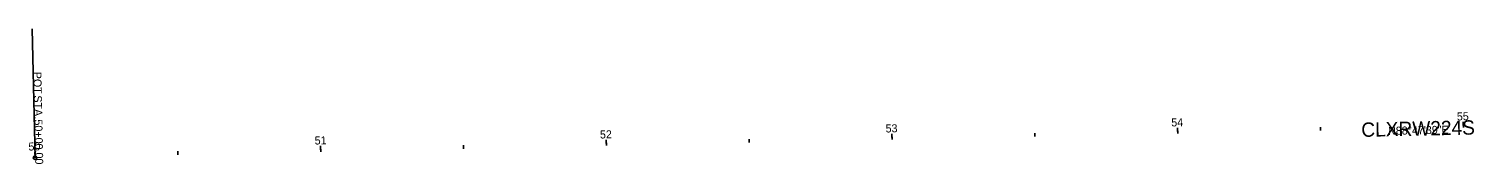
# Model space of a CAD drawing. Extents: x 2402033 to 2407435, y 498456 to 498900.
# Drawn here: x 2402033 to 2402538, y 498643 to 498690 of the extents above; entities that cross this region are included whole.
import ezdxf

# ---------------------------------------------------------------- set-up
doc = ezdxf.new("R2010")
doc.units = 0
for name, color, linetype in [('DR_P_Ditch', 7, 'Continuous'), ('DT_P_Graded_Shoulder', 7, 'Continuous'), ('DV_X_Property_Line', 7, 'Continuous'), ('MD_P_DNC', 7, 'Continuous'), ('MD_P_GRADE_BREAK', 7, 'Continuous'), ('RW_P_Esmt_CH', 7, 'Continuous'), ('RW_P_Esmt_SH', 7, 'Continuous'), ('RW_P_Esmt_TMP', 7, 'Continuous'), ('RW_X_CL_1000_Distances', 7, 'Continuous'), ('RW_X_Esmt_RR', 7, 'Continuous'), ('RW_X_Esmt_SH', 7, 'Continuous'), ('RW_X_Parent_Tract_Area', 7, 'Continuous')]:
    doc.layers.add(name, color=color, linetype=linetype)

msp = doc.modelspace()

# ---------------------------------------------------------------- linework, layer by layer
at = {"layer": 'DR_P_Ditch'}
for p, q in [((2402534.58, 498655.93), (2402534.55, 498657.13)), ((2402034.69, 498645.41), (2402034.65, 498647.41))]:
    msp.add_line(p, q, dxfattribs=at)
at = {"layer": 'DV_X_Property_Line'}
msp.add_line((2402034.69, 498645.41), (2402033.74, 498690.4), dxfattribs=at)
msp.add_circle((2402034.69, 498645.41), 0.6, dxfattribs=at)
at = {"layer": 'RW_P_Esmt_CH'}
for p, q in [((2402534.58, 498655.93), (2402534.54, 498657.93)), ((2402334.62, 498651.72), (2402334.6, 498652.92)), ((2402434.6, 498653.83), (2402434.57, 498655.02)), ((2402034.69, 498645.41), (2402034.65, 498647.41)), ((2402134.67, 498647.51), (2402134.64, 498648.71)), ((2402234.64, 498649.62), (2402234.62, 498650.82))]:
    msp.add_line(p, q, dxfattribs=at)
at = {"layer": 'RW_P_Esmt_SH'}
msp.add_line((2402034.69, 498645.41), (2402033.74, 498690.4), dxfattribs=at)
msp.add_circle((2402034.69, 498645.41), 0.6, dxfattribs=at)
at = {"layer": 'RW_X_Esmt_SH'}
for p, q in [((2402534.58, 498655.93), (2402534.54, 498657.93)), ((2402334.62, 498651.72), (2402334.58, 498653.72)), ((2402384.61, 498652.77), (2402384.59, 498653.97)), ((2402434.6, 498653.83), (2402434.56, 498655.82)), ((2402484.59, 498654.88), (2402484.56, 498656.08)), ((2402034.69, 498645.41), (2402034.65, 498647.41)), ((2402084.68, 498646.46), (2402084.65, 498647.66)), ((2402134.67, 498647.51), (2402134.62, 498649.51)), ((2402184.65, 498648.56), (2402184.63, 498649.76)), ((2402234.64, 498649.62), (2402234.6, 498651.62)), ((2402284.63, 498650.67), (2402284.61, 498651.87))]:
    msp.add_line(p, q, dxfattribs=at)
at = {"layer": 'RW_X_Parent_Tract_Area'}
msp.add_line((2402034.69, 498645.41), (2402033.74, 498690.4), dxfattribs=at)
msp.add_circle((2402034.69, 498645.41), 0.6, dxfattribs=at)

# ---------------------------------------------------------------- texts
at = {"layer": 'DR_P_Ditch'}
msp.add_text('50', height=2.8, rotation=1.2059, dxfattribs=at).set_placement((2402032.41, 498647.9))
at = {"layer": 'DT_P_Graded_Shoulder'}
msp.add_text('CLXRW224S', height=5, rotation=1.2059, dxfattribs=at).set_placement((2402498.92, 498652.68))
at = {"layer": 'DV_X_Property_Line'}
for s, p in [('POT', (2402034.1, 498675.4)), (' STA. ', (2402034.25, 498668.2)), ('50+00.00', (2402034.45, 498658.75))]:
    msp.add_text(s, height=2.8, rotation=271.2059, dxfattribs=at).set_placement(p)
at = {"layer": 'MD_P_DNC'}
msp.add_text('CLXRW224S', height=5, rotation=1.2059, dxfattribs=at).set_placement((2402498.92, 498652.68))
at = {"layer": 'MD_P_GRADE_BREAK'}
msp.add_text('CLXRW224S', height=5, rotation=1.2059, dxfattribs=at).set_placement((2402498.92, 498652.68))
at = {"layer": 'RW_P_Esmt_CH'}
for s, p in [('55', (2402532.34, 498658.42)), ('50', (2402032.41, 498647.9))]:
    msp.add_text(s, height=2.8, rotation=1.2059, dxfattribs=at).set_placement(p)
at = {"layer": 'RW_P_Esmt_SH'}
for s, p in [('POT', (2402034.1, 498675.4)), (' STA. ', (2402034.25, 498668.2)), ('50+00.00', (2402034.45, 498658.75))]:
    msp.add_text(s, height=2.8, rotation=271.2059, dxfattribs=at).set_placement(p)
at = {"layer": 'RW_P_Esmt_TMP'}
msp.add_text('N88°47\'39"E', height=2.8, rotation=1.2059, dxfattribs=at).set_placement((2402508.26, 498653.38))
at = {"layer": 'RW_X_CL_1000_Distances'}
msp.add_text('N88°47\'39"E', height=2.8, rotation=1.2059, dxfattribs=at).set_placement((2402508.26, 498653.38))
at = {"layer": 'RW_X_Esmt_RR'}
msp.add_text('N88°47\'39"E', height=2.8, rotation=1.2059, dxfattribs=at).set_placement((2402508.26, 498653.38))
at = {"layer": 'RW_X_Esmt_SH'}
for s, p in [('54', (2402432.39, 498656.32)), ('55', (2402532.34, 498658.42)), ('51', (2402132.58, 498650.01)), ('52', (2402232.43, 498652.11)), ('53', (2402332.41, 498654.22)), ('50', (2402032.41, 498647.9))]:
    msp.add_text(s, height=2.8, rotation=1.2059, dxfattribs=at).set_placement(p)
at = {"layer": 'RW_X_Parent_Tract_Area'}
for s, p in [('POT', (2402034.1, 498675.4)), (' STA. ', (2402034.25, 498668.2)), ('50+00.00', (2402034.45, 498658.75))]:
    msp.add_text(s, height=2.8, rotation=271.2059, dxfattribs=at).set_placement(p)

doc.saveas('drawing.dxf')
